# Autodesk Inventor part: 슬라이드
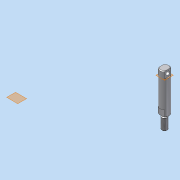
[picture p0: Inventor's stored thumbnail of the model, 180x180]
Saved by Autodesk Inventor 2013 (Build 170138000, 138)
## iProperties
Company: 한국ATC센터
Created: 2009-02
Document SubType Name: Modeling
Designer: KYOUNG IL JANG
Density: 2.71 g/cm^3
Material: 알루미늄-6061
Mass: 23.7345 g
Surface Area: 33.7774 cm^2
Volume: 8.75813 cm^3
Vendor: CBT Solutions
Part Number: 슬라이드
Author: KYOUNG IL JANG
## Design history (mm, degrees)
node "작업 평면1"
sketch "스케치1"
  geometry: L1 (126.442, 94.902)-(135.988, 94.902); L2 (135.988, 94.902)-(135.988, 85.356); L3 (135.988, 85.356)-(126.442, 85.356); L4 (126.442, 85.356)-(126.442, 94.902); A1 r 6.75 centre (131.215, 90.129) between (126.442, 94.902) and (126.442, 85.356); A2 r 6.75 centre (131.215, 90.129) between (135.988, 94.902) and (126.442, 94.902); A3 r 6.75 centre (131.215, 90.129) between (135.988, 85.356) and (135.988, 94.902); A4 r 6.75 centre (131.215, 90.129) between (126.442, 85.356) and (135.988, 85.356); 2 further points
  constraints: 8 end point, 8 point on circle, 4 centre point, 2 coincident, 1 horizontal, 9 other
  dimensions: "d0" = 13.5 diameter of A1
extrude "돌출1" new body sketch "스케치1" distance "d1" = 60; taper "d2" = 0 deg
sketch "스케치2"
  geometry: C1 r 4 at (0, 0); 1 further point
  constraints: 1 centre point, 1 coincident
  dimensions: "d3" = 8 diameter of C1
extrude "돌출2" join sketch "스케치2" distance "d4" = 20; taper "d5" = 0 deg
sketch "스케치3"
  geometry: C1 r 4 at (0, 0) reference; C2 r 3 at (0, 0); 1 further point
  constraints: 1 centre point
  dimensions: "d6" = 1 radial gap between concentric circles of C1 C2
extrude "돌출3" cut sketch "스케치3" distance "d7" = 2; taper "d8" = 0 deg
chamfer "모따기1" distance "d9" = 1; stored, may be unused: second distance "d10" = 2, angle "d11" = 45 deg
feature "스레드1" dims "d12" = 10, "d13" = 0
chamfer "모따기2" distance "d14" = 1; stored, may be unused: second distance "d15" = 2, angle "d16" = 45 deg
extrude "돌출4" cut sketch "스케치1" distance "d18" = 10; taper "d19" = 0 deg
node "작업 평면2"
chamfer "모따기3" distance "d23" = 1; stored, may be unused: second distance "d24" = 2, angle "d25" = 45 deg
extrude "돌출5" cut sketch "스케치1" stored distance "d21" = 10; taper "d22" = 0 deg
sketch "스케치4"
  geometry: L1 (-10, 7.979)-(-10, 1.567) reference; 2 further points
  constraints: 1 horizontal alignment
  dimensions: "d26" = 5 distance from line of point (-5, 4.773) L1
hole "구멍1" sketch "스케치4" at (-5, 4.773) diameter "d27" = 5.5; stored, may be unused: countersink angle "d31" = 90 deg, drill point angle "d33" = 118 deg; dims "d28" = 6, "d29" = 4, "d30" = 2, "d32" = 8
node "솔리드1"
